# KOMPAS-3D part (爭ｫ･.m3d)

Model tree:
1. Эскиз:2
2. Операция выдавливания:1
     Расстояние 1 = 35; Угол 1 = 4
3. Эскиз:3
4. Вырезать элемент выдавливания:1
     Расстояние 2 = 35; Угол 2 = 1.91; Расстояние 1 = 10
5. Оболочка:2
     Толщина стенки 2 = 1
6. Эскиз:8
7. Вырезать элемент выдавливания:4
     Расстояние 2 = 11.1672; Расстояние 1 = 11.1672
8. Эскиз:10
9. Операция выдавливания:4
     Расстояние 1 = 1; Угол 2 = 1.98
10. Эскиз:16
11. Операция выдавливания:9
     Расстояние 1 = 2; Расстояние 2 = 1; Угол 2 = 4
12. Эскиз:17
13. Операция выдавливания:10
     Расстояние 1 = 3; Расстояние 2 = 15; Угол 2 = 4
14. Эскиз:18
15. Операция выдавливания:11
     Расстояние 1 = 1; Расстояние 2 = 15; Угол 2 = 4
16. Скругление:1
     Радиус = 1
17. Скругление:2
     Радиус = 1
18. Скругление:3
     Радиус = 1
19. Эскиз:22
20. Вырезать элемент выдавливания:8
     Расстояние 1 = 15
21. Эскиз:23
22. Вырезать элемент выдавливания:9
     Расстояние 1 = 10
23. Эскиз:24
24. Вырезать элемент выдавливания:10
     Расстояние 1 = 15
